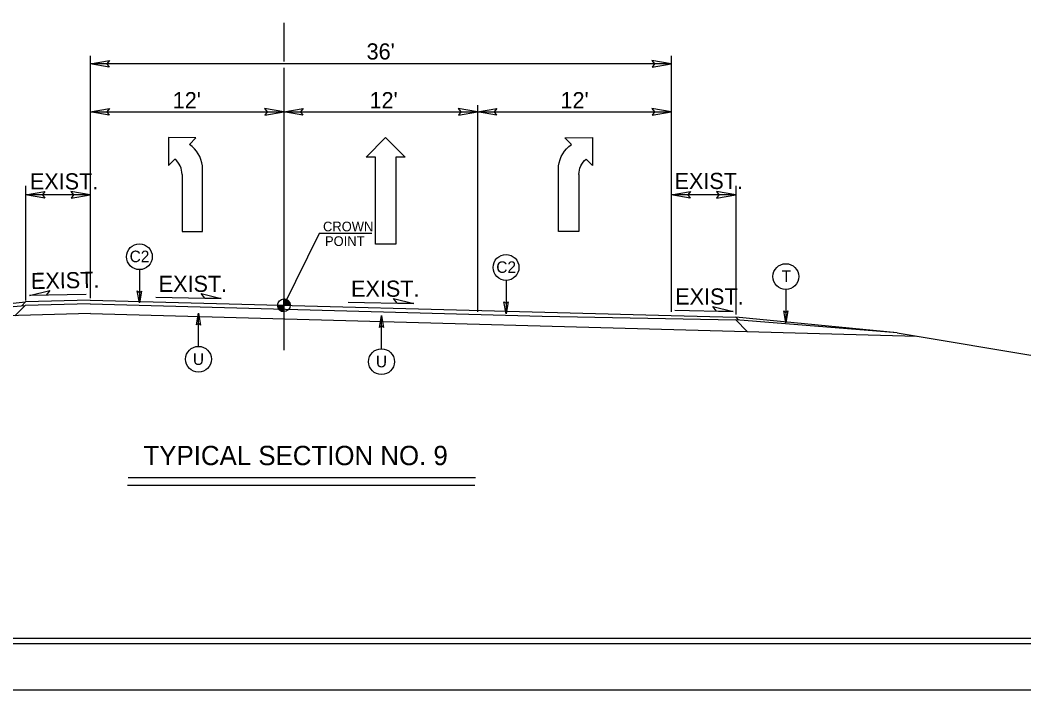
# Model space of a CAD drawing. Extents: x 957297 to 961629, y 830661 to 840840.
# Drawn here: x 959367.2 to 959851.8, y 835897.1 to 836220.4 of the extents above; entities that cross this region are included whole.
import ezdxf

# ---------------------------------------------------------------- set-up
doc = ezdxf.new("R2010")
doc.units = 0
for name, color, linetype in [('Default', 7, 'Continuous'), ('Old_Level_1', 7, 'Continuous'), ('Old_Level_11', 7, 'Continuous'), ('Prop Dimension', 7, 'Continuous'), ('Prop Dimension Text', 7, 'Continuous'), ('Prop Lane Arrow CELL', 7, 'Continuous'), ('Prop XS Finish Grade Earthwork', 7, 'Continuous'), ('Sheet Plot Border Inside CELL', 7, 'Continuous'), ('Sheet Plot Border Outside CELL', 7, 'Continuous'), ('Sheet Typical CELL', 7, 'Continuous'), ('Typical ID Circle CELL', 7, 'Continuous'), ('Typical Terminator CELL', 7, 'Continuous'), ('Typical Text Grade Point CELL', 7, 'Continuous'), ('Typical Text ID Circle CELL', 7, 'Continuous')]:
    doc.layers.add(name, color=color, linetype=linetype)

# ---------------------------------------------------------------- blocks, each defined once
blk = doc.blocks.new('Lane Arrow Left Turn')
at = {"layer": 'Prop Lane Arrow CELL'}
for p, q in [((0, 0), (-4.5, 0.05)), ((-4.5, 0.05), (-3.45, -1)), ((-0.05, -4.4), (0, 0)), ((-5.95, -2.15), (-15.1, -2.15)), ((-15.1, -2.15), (-15.1, -5.45)), ((-1.1, -3.35), (-0.05, -4.4)), ((-15.1, -5.45), (-4.55, -5.45))]:
    blk.add_line(p, q, dxfattribs=at)
for centre, radius, start, end in [((-5.94, 1.11), 3.27, 270, 319.6582), ((-5.34, -0.27), 5.25, 278.6761, 323.9878)]:
    blk.add_arc(centre, radius, start, end, dxfattribs=at)
blk = doc.blocks.new('Lane Arrow Through')
at = {"layer": 'Prop Lane Arrow CELL'}
for p, q in [((-3.15, 1.6), (-3.15, 3.1)), ((-3.15, 3.1), (0, 0)), ((-17.15, 1.6), (-3.15, 1.6)), ((-17.15, -1.7), (-17.15, 1.6)), ((0, 0), (-3.15, -3.2)), ((-3.15, -1.7), (-17.15, -1.7)), ((-3.15, -3.2), (-3.15, -1.7))]:
    blk.add_line(p, q, dxfattribs=at)

msp = doc.modelspace()

# ---------------------------------------------------------------- linework, layer by layer
at = {"layer": 'Default'}
for p, q in [((959494.54, 836219.07), (959494.54, 836200.41)), ((959494.54, 836197.37), (959494.54, 836061.05))]:
    msp.add_line(p, q, dxfattribs=at)
at = {"layer": 'Old_Level_1'}
for p, q in [((959401.06, 836176.05), (959494.54, 836176.05)), ((959494.54, 836176.05), (959588.02, 836176.05)), ((959588.02, 836176.05), (959681.5, 836176.05)), ((959307.35, 836077.65), (959369.9, 836084.37)), ((959369.9, 836084.37), (959368.04, 836082.5)), ((959401.01, 836085.22), (959369.9, 836084.37)), ((959399.11, 836088.02), (959371.78, 836087.47)), ((959401.06, 836085.22), (959681.5, 836077.83)), ((959432.75, 836086.64), (959464.36, 836086.01)), ((959494.54, 836082.75), (959494.54, 836085.82)), ((959525.61, 836084.27), (959557.21, 836083.64)), ((959307.35, 836077.65), (959369.67, 836082.63)), ((959369.67, 836082.63), (959364.76, 836077.73)), ((959491.48, 836082.75), (959494.54, 836082.75)), ((959497.6, 836082.75), (959494.54, 836082.75)), ((959494.54, 836079.71), (959494.54, 836082.75)), ((959494.54, 836082.75), (959494.54, 836079.71)), ((959683.31, 836080.31), (959711.39, 836079.75)), ((959401.25, 836078.72), (959800.11, 836067.85)), ((959619.18, 836077.55), (959712.66, 836075.68)), ((959681.5, 836077.83), (959712.66, 836077.01)), ((959712.66, 836077.01), (959714.11, 836075.56)), ((959790.56, 836069.44), (959712.66, 836075.68)), ((959712.66, 836075.68), (959718.25, 836070.08)), ((959790.56, 836069.44), (960024.26, 836030.49)), ((959587.08, 835999.56), (959419.39, 835999.56)), ((959586.8, 835995.75), (959419.11, 835995.75))]:
    msp.add_line(p, q, dxfattribs=at)
for points in [[(959494.58, 836085.82), (959494.58, 836085.82), (959494.58, 836082.75)], [(959494.63, 836085.82), (959494.63, 836082.75)], [(959494.69, 836085.81), (959494.69, 836082.75)], [(959494.76, 836085.81), (959494.76, 836082.75)], [(959494.82, 836085.81), (959494.82, 836082.75)], [(959494.88, 836085.81), (959494.88, 836082.75)], [(959494.94, 836085.79), (959494.94, 836082.75)], [(959495, 836085.79), (959495, 836082.75)], [(959495.06, 836085.77), (959495.06, 836082.75)], [(959495.12, 836085.77), (959495.12, 836082.75)], [(959495.19, 836085.75), (959495.19, 836082.75)], [(959495.25, 836085.74), (959495.25, 836082.75)], [(959495.31, 836085.72), (959495.31, 836082.75)], [(959495.37, 836085.7), (959495.37, 836082.75)], [(959495.44, 836085.69), (959495.44, 836082.75)], [(959495.49, 836085.66), (959495.49, 836082.75)], [(959495.56, 836085.65), (959495.55, 836082.75)], [(959495.61, 836085.62), (959495.61, 836082.75)], [(959495.67, 836085.61), (959495.67, 836082.75)], [(959495.74, 836085.58), (959495.74, 836082.75)], [(959495.8, 836085.56), (959495.8, 836082.75)], [(959495.86, 836085.52), (959495.86, 836082.75)], [(959495.91, 836085.5), (959495.91, 836082.75)], [(959495.97, 836085.47), (959495.97, 836082.75)], [(959496.04, 836085.43), (959496.04, 836082.75)], [(959496.1, 836085.4), (959496.1, 836082.75)], [(959496.16, 836085.36), (959496.16, 836082.75)], [(959496.23, 836085.31), (959496.23, 836082.75)], [(959496.29, 836085.27), (959496.29, 836082.75)], [(959496.34, 836085.24), (959496.34, 836082.75)], [(959496.41, 836085.18), (959496.41, 836082.75)], [(959496.47, 836085.14), (959496.47, 836082.75)], [(959496.53, 836085.09), (959496.53, 836082.75)], [(959496.59, 836085.03), (959496.59, 836082.75)], [(959496.65, 836084.97), (959496.65, 836082.75)], [(959496.72, 836084.91), (959496.72, 836082.75)], [(959496.77, 836084.85), (959496.77, 836082.75)], [(959496.83, 836084.79), (959496.83, 836082.75)], [(959496.89, 836084.72), (959496.89, 836082.75)], [(959496.95, 836084.63), (959496.95, 836082.75)], [(959497.02, 836084.55), (959497.02, 836082.75)], [(959497.08, 836084.47), (959497.08, 836082.75)], [(959497.14, 836084.38), (959497.14, 836082.75)], [(959497.2, 836084.27), (959497.2, 836082.75)], [(959497.26, 836084.17), (959497.26, 836082.75)], [(959497.32, 836084.02), (959497.32, 836082.75)], [(959497.39, 836083.88), (959497.39, 836082.75)], [(959497.45, 836083.72), (959497.45, 836082.75)], [(959401.06, 836083.49), (959369.67, 836082.63)], [(959401.06, 836083.49), (959619.18, 836077.55)], [(959491.5, 836082.75), (959491.5, 836082.43)], [(959491.56, 836082.75), (959491.56, 836082.07)], [(959491.62, 836082.75), (959491.62, 836081.85)], [(959491.68, 836082.75), (959491.68, 836081.67)], [(959491.75, 836082.75), (959491.75, 836081.52)], [(959491.81, 836082.75), (959491.81, 836081.39)], [(959491.87, 836082.75), (959491.87, 836081.28)], [(959491.93, 836082.75), (959491.93, 836081.17)], [(959492, 836082.75), (959492, 836081.08)], [(959492.06, 836082.75), (959492.06, 836080.99)], [(959492.12, 836082.75), (959492.12, 836080.9)], [(959492.18, 836082.75), (959492.18, 836080.83)], [(959492.24, 836082.75), (959492.24, 836080.76)], [(959492.29, 836082.75), (959492.29, 836080.69)], [(959492.35, 836082.75), (959492.35, 836080.62)], [(959492.42, 836082.75), (959492.42, 836080.57)], [(959492.48, 836082.75), (959492.48, 836080.51)], [(959492.54, 836082.75), (959492.54, 836080.45)], [(959492.6, 836082.75), (959492.6, 836080.41)], [(959492.67, 836082.75), (959492.67, 836080.35)], [(959492.72, 836082.75), (959492.72, 836080.31)], [(959492.79, 836082.75), (959492.79, 836080.26)], [(959492.85, 836082.75), (959492.85, 836080.22)], [(959492.91, 836082.75), (959492.91, 836080.17)], [(959492.98, 836082.75), (959492.98, 836080.13)], [(959493.04, 836082.75), (959493.04, 836080.1)], [(959493.1, 836082.75), (959493.1, 836080.06)], [(959493.15, 836082.75), (959493.15, 836080.05)], [(959493.21, 836082.75), (959493.21, 836080.01)], [(959493.28, 836082.75), (959493.28, 836079.97)], [(959493.34, 836082.75), (959493.34, 836079.96)], [(959493.4, 836082.75), (959493.4, 836079.92)], [(959493.46, 836082.75), (959493.46, 836079.91)], [(959493.52, 836082.75), (959493.52, 836079.88)], [(959493.58, 836082.75), (959493.58, 836079.86)], [(959493.64, 836082.75), (959493.64, 836079.84)], [(959493.7, 836082.75), (959493.7, 836079.82)], [(959493.76, 836082.75), (959493.76, 836079.81)], [(959493.83, 836082.75), (959493.83, 836079.8)], [(959493.89, 836082.75), (959493.89, 836079.78)], [(959493.95, 836082.75), (959493.95, 836079.76)], [(959494.01, 836082.75), (959494.01, 836079.76)], [(959494.07, 836082.75), (959494.07, 836079.75)], [(959494.13, 836082.75), (959494.13, 836079.72)], [(959494.2, 836082.75), (959494.2, 836079.72)], [(959494.26, 836082.75), (959494.26, 836079.72)], [(959494.32, 836082.75), (959494.32, 836079.71)], [(959494.38, 836082.75), (959494.38, 836079.71)], [(959494.43, 836082.75), (959494.43, 836079.71)], [(959494.49, 836082.75), (959494.49, 836079.71), (959494.49, 836079.71)], [(959497.51, 836083.51), (959497.51, 836082.75)], [(959497.57, 836083.2), (959497.57, 836082.75)], [(959401.25, 836078.72), (959296.7, 836075.87)]]:
    msp.add_lwpolyline(points, dxfattribs=at)
msp.add_circle((959494.54, 836082.76), 3.06, dxfattribs=at)
for start, end in [(359.9905, 89.9905), (179.9905, 269.9905)]:
    msp.add_arc((959494.54, 836082.76), 3.06, start, end, dxfattribs=at)
at = {"layer": 'Old_Level_11'}
for p, q in [((959371.78, 836087.47), (959381.53, 836089.9)), ((959381.53, 836089.9), (959379.8, 836087.63)), ((959379.8, 836087.63), (959371.78, 836087.47)), ((959456.35, 836086.16), (959454.62, 836088.42)), ((959454.62, 836088.42), (959464.36, 836086.01)), ((959464.36, 836086.01), (959456.35, 836086.16)), ((959549.21, 836083.8), (959547.48, 836086.06)), ((959547.48, 836086.06), (959557.21, 836083.64)), ((959557.21, 836083.64), (959549.21, 836083.8)), ((959703.39, 836079.91), (959701.66, 836082.16)), ((959701.66, 836082.16), (959711.39, 836079.75)), ((959711.39, 836079.75), (959703.39, 836079.91))]:
    msp.add_line(p, q, dxfattribs=at)
at = {"layer": 'Prop Dimension'}
for p, q in [((959401.06, 836203.09), (959401.06, 836086.19)), ((959681.5, 836203.09), (959681.5, 836079.61)), ((959681.5, 836199.22), (959401.06, 836199.22)), ((959588.02, 836179.34), (959588.02, 836079.61)), ((959369.9, 836140.37), (959369.9, 836085.03)), ((959712.66, 836140.37), (959712.66, 836078.23)), ((959401.06, 836136.08), (959369.9, 836136.08)), ((959712.66, 836136.08), (959681.5, 836136.08))]:
    msp.add_line(p, q, dxfattribs=at)
at = {"layer": 'Prop XS Finish Grade Earthwork'}
msp.add_line((959790.56, 836069.44), (959712.66, 836077.01), dxfattribs=at)
at = {"layer": 'Sheet Plot Border Inside CELL'}
msp.add_lwpolyline([(960390.3, 836974.7), (958723.8, 836974.7), (958723.8, 835919.6), (960390.3, 835919.6)], close=True, dxfattribs=at)
at = {"layer": 'Sheet Plot Border Outside CELL'}
msp.add_lwpolyline([(960394.8, 836997.15), (958710.8, 836997.15), (958710.8, 835897.15), (960394.8, 835897.15)], close=True, dxfattribs=at)
at = {"layer": 'Sheet Typical CELL'}
msp.add_lwpolyline([(960377.8, 836972.15), (958877.8, 836972.15), (958877.8, 835922.15), (960377.8, 835922.15)], close=True, dxfattribs=at)
at = {"layer": 'Typical ID Circle CELL'}
for p, q in [((959424.82, 836099.95), (959424.82, 836083.86)), ((959601.79, 836094.78), (959601.79, 836078.69)), ((959736.84, 836090.36), (959736.84, 836074.27)), ((959453.33, 836062.92), (959453.33, 836079.01)), ((959541.67, 836061.75), (959541.67, 836077.84))]:
    msp.add_line(p, q, dxfattribs=at)
for centre in [(959424.82, 836106.17), (959601.79, 836101), (959736.84, 836096.59), (959453.33, 836056.7), (959541.67, 836055.53)]:
    msp.add_circle(centre, 6.23, dxfattribs=at)
at = {"layer": 'Typical Terminator CELL'}
for points in [[(959410.28, 836197.63), (959401.06, 836199.22), (959410.33, 836200.86), (959409.15, 836199.22)], [(959672.28, 836197.63), (959681.5, 836199.22), (959672.23, 836200.86), (959673.4, 836199.22)], [(959410.28, 836174.47), (959401.06, 836176.05), (959410.33, 836177.69), (959409.15, 836176.05)], [(959485.32, 836174.47), (959494.54, 836176.05), (959485.27, 836177.69), (959486.44, 836176.05)], [(959503.76, 836174.47), (959494.54, 836176.05), (959503.81, 836177.69), (959502.63, 836176.05)], [(959578.8, 836174.47), (959588.02, 836176.05), (959578.75, 836177.69), (959579.92, 836176.05)], [(959597.24, 836174.47), (959588.02, 836176.05), (959597.29, 836177.69), (959596.11, 836176.05)], [(959672.28, 836174.47), (959681.5, 836176.05), (959672.23, 836177.69), (959673.4, 836176.05)], [(959379.12, 836134.49), (959369.9, 836136.08), (959379.17, 836137.72), (959377.99, 836136.08)], [(959391.84, 836134.49), (959401.06, 836136.08), (959391.79, 836137.72), (959392.96, 836136.08)], [(959690.72, 836134.49), (959681.5, 836136.08), (959690.77, 836137.72), (959689.59, 836136.08)], [(959703.44, 836134.49), (959712.66, 836136.08), (959703.39, 836137.72), (959704.56, 836136.08)], [(959425.81, 836089.62), (959424.82, 836083.86), (959423.8, 836089.66), (959424.82, 836088.92)], [(959602.79, 836084.45), (959601.79, 836078.69), (959600.77, 836084.48), (959601.79, 836083.75)], [(959452.34, 836073.24), (959453.33, 836079.01), (959454.36, 836073.21), (959453.33, 836073.95)], [(959737.83, 836080.04), (959736.84, 836074.27), (959735.82, 836080.07), (959736.84, 836079.33)], [(959540.68, 836072.08), (959541.67, 836077.84), (959542.7, 836072.04), (959541.67, 836072.78)]]:
    msp.add_lwpolyline(points, close=True, dxfattribs=at)
at = {"layer": 'Typical Text Grade Point CELL'}
for p, q in [((959511.65, 836117.32), (959494.54, 836082.75)), ((959536.98, 836117.32), (959511.65, 836117.32))]:
    msp.add_line(p, q, dxfattribs=at)

# ---------------------------------------------------------------- block references
at = {"layer": 'Old_Level_1', "xscale": 3}
for name, p, yscale, rotation in [('Lane Arrow Left Turn', (959438.93, 836163.66), 3, 90), ('Lane Arrow Through', (959543.56, 836163.66), 3, 90), ('Lane Arrow Left Turn', (959643.45, 836163.66), -3, 90.00000000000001)]:
    msp.add_blockref(name, p, dxfattribs=dict(at, yscale=yscale, rotation=rotation))

# ---------------------------------------------------------------- texts
at = {"layer": 'Old_Level_1'}
msp.add_text('TYPICAL SECTION NO. 9', height=9.3239, dxfattribs=at).set_placement((959426.8, 836005.6))
at = {"layer": 'Old_Level_11'}
for s, p in [('CROWN', (959513.45, 836118.43)), ('POINT', (959514.4, 836111.36))]:
    msp.add_text(s, height=4.671, dxfattribs=at).set_placement(p)
at = {"layer": 'Prop Dimension'}
for s, p in [("36'", (959534.48, 836201.33)), ("12'", (959440.91, 836177.81)), ("12'", (959535.9, 836177.81)), ("12'", (959628.09, 836177.81))]:
    msp.add_text(s, height=7.801, rotation=360, dxfattribs=at).set_placement(p)
for p in [(959683.12, 836138.84), (959371.94, 836138.64)]:
    msp.add_text('EXIST.', height=7.801, dxfattribs=at).set_placement(p)
at = {"layer": 'Prop Dimension Text'}
for rotation, p in [(1.1839, (959372.53, 836090.54)), (360, (959434.12, 836089.21)), (360, (959526.98, 836086.85)), (360, (959683.46, 836083.1))]:
    msp.add_text('EXIST.', height=7.801, rotation=rotation, dxfattribs=at).set_placement(p)
at = {"layer": 'Typical Text ID Circle CELL'}
for s, height, p in [('C2', 5.572, (959420.11, 836103.54)), ('C2', 5.572, (959597.08, 836098.37)), ('T', 5.57, (959734.8, 836093.96)), ('U', 5.57, (959450.63, 836053.95)), ('U', 5.57, (959538.97, 836052.79))]:
    msp.add_text(s, height=height, dxfattribs=at).set_placement(p)

doc.saveas('drawing.dxf')
